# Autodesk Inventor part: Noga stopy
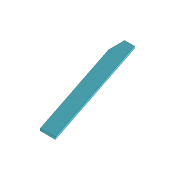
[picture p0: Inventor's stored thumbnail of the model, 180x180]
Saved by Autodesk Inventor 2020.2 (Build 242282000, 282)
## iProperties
Created: 2011-11
Part Number: Noga stopy
Material: Stal
Document SubType Name: Modeling
Designer: F.Stasiak
Density: 7.85 g/cm^3
Mass: 188.739 g
Surface Area: 140.536 cm^2
Volume: 24.0432 cm^3
Appearance: Niebieska z odcieniem szarości
Catalog Web Link: www.expertbooks.pl
Manager: www.cadconsulting.pl
Company: Fabian Stasiak CAD Consulting
Author: F.Stasiak
Subject: Zbiór ćwiczeń. Autodesk Inventor 2020. Kurs Professional
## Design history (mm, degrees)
sketch "Szkic1"
  geometry: L1 (-63, 220)-(-63, 190); L2 (-63, 190)-(0, 0); L3 (0, 0)-(28, 0); L4 (28, 0)-(-44.947, 220); L5 (-44.947, 220)-(-63, 220); 1 further point
  constraints: 10 end point, 2 parallel, 1 coincident, 1 perpendicular, 1 vertical
  dimensions: "d0" = 220 distance between parallel lines of L5 L3; "d2" = 28 distance of L2.end L3.end; "d3" = 30 distance of L1.start L1.end; "d6" = 63 distance from line of point (0, 0) L1
extrude "Wyciągnięcie proste1" new body sketch "Szkic1" stored distance "d4" = 4; taper "d5" = 0 deg
node "Bryła1"
